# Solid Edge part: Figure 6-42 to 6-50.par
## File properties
Author: Ashutosh-CADCIM
Template: Iso Metric Part.par
Last saved by: Ashutosh-CADCIM
Revision: 1
Application: Solid Edge
Accuracy: 0.990
Username: Ashutosh-CADCIM
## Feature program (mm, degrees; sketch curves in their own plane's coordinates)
sketch for "unnamed Protrusion 1" plane through (0, 0, 0) normal (0, 0, 1) x-axis (1, 0, 0)
  line (-100, -100) -> (100, -100)
  line (100, -100) -> (100, 100)
  line (100, 100) -> (-100, 100)
  line (-100, 100) -> (-100, -100)
extrude "unnamed Protrusion 1" add finite 20 symmetric
sketch for "ExtrudedCutout_1" plane through (0, 0, 10) normal (0, 0, 1) x-axis (0, 1, 0)
  circle centre (-78.0723, 81.8892) radius 9.7713
extrude "ExtrudedCutout_1" cut finite 64.5069 along -normal
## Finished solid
Body 1: solid body, 7 faces, 14 edges, 8 vertices.
  Faces by surface: plane 6, cylinder 1
  Edges by curve: line 12, circle 2
Bounding box of the edges (mm): 200.000 x 200.000 x 20.000, from (-100, -100, -10) to (100, 100, 10).
Cylindrical faces by radius (mm): R9.7713 x1
Planar faces by outward normal: +x 1, +y 1, +z 1, -x 1, -y 1, -z 1
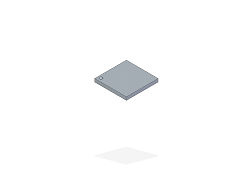
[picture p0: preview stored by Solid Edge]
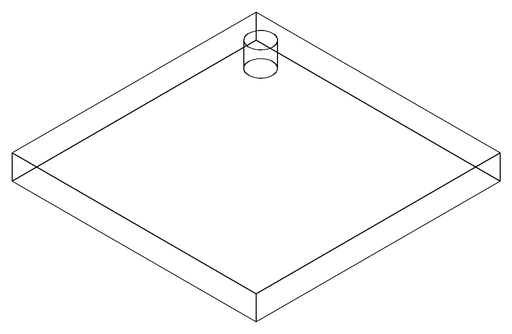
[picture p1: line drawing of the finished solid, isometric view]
